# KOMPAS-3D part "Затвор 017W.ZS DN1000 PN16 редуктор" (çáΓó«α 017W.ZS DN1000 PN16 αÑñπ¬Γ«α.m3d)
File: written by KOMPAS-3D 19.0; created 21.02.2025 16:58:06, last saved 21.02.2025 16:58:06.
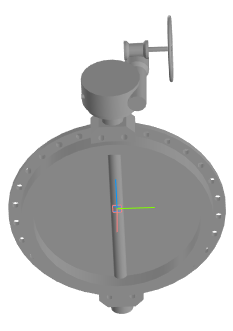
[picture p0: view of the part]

Document properties: Автор: Евгений; Полное имя файла: Затвор 017W.ZS DN1000 PN16 редуктор.a3d

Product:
- Part/product: Затвор 017W.ZS DN1000 PN16 редуктор
    Масса: 884.167

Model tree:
1. Операция без истории:1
